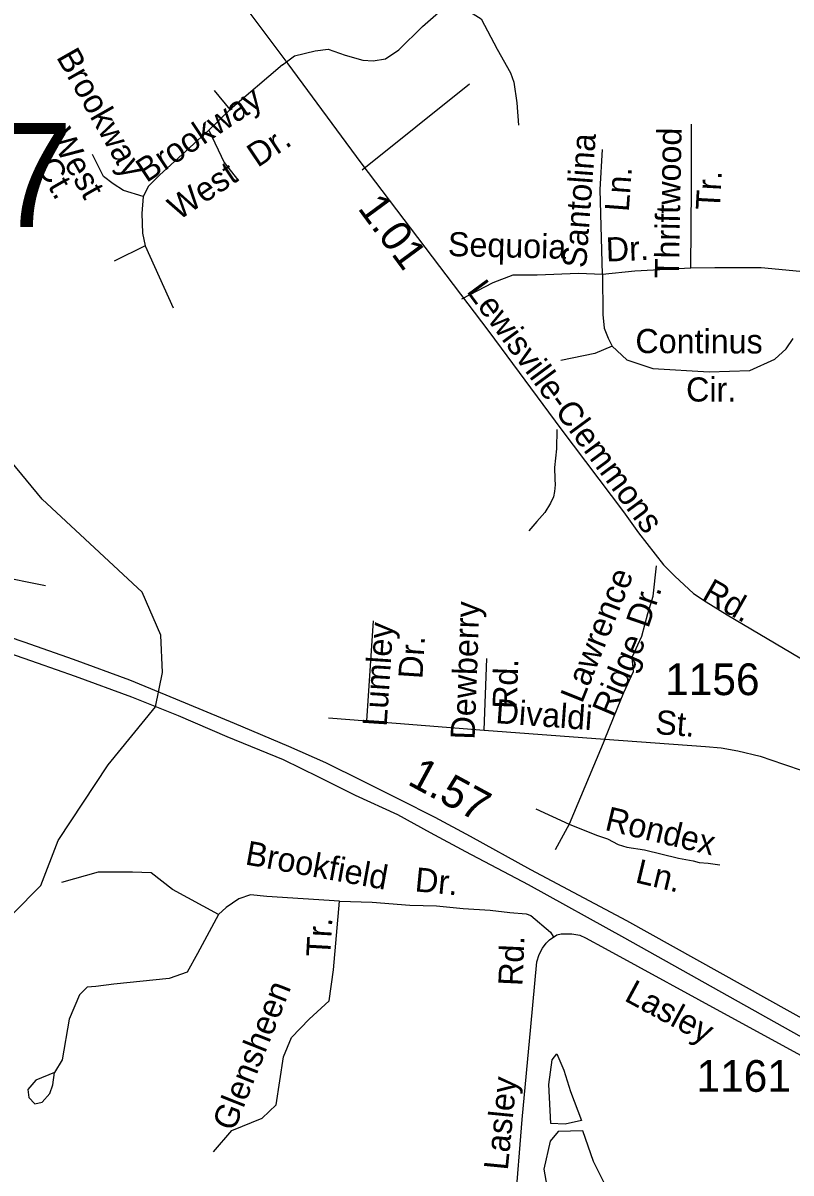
# Model space of a CAD drawing. Extents: x 1547597 to 1699558, y 810033 to 920809.
# Drawn here: x 1580417 to 1583442, y 851817 to 856344 of the extents above; entities that cross this region are included whole.
import ezdxf

# ---------------------------------------------------------------- set-up
doc = ezdxf.new("R2010")
doc.units = 0
for name, color, linetype in [('Exist Hydrographic Misc Water Feature', 7, 'Continuous'), ('Exist Road Non-System Type 51', 7, 'Continuous'), ('Exist Road Non-System Type 51 Label', 7, 'Continuous'), ('Exist Road Primary US Divided Attributed', 7, 'Continuous'), ('Exist Road Primary US Mileage Hundredths English Label', 7, 'Continuous'), ('Exist Road Secondary Mileage Hundredths English Label', 7, 'Continuous'), ('Exist Road Secondary Structure Standard Bridge Number Label', 7, 'Continuous'), ('Exist Road Secondary Type 51 Attributed', 7, 'Continuous'), ('Exist Road Secondary Type 51 Label', 7, 'Continuous'), ('Exist Road Secondary Type 51 Number Label', 7, 'Continuous')]:
    doc.layers.add(name, color=color, linetype=linetype)

msp = doc.modelspace()

# ---------------------------------------------------------------- linework, layer by layer
at = {"layer": 'Exist Hydrographic Misc Water Feature'}
for points in [[(1580376.5, 852836.6), (1580486.5, 852949.2), (1580555.5, 853125.1), (1580751.5, 853423.1), (1580938.5, 853652.4), (1580965.5, 853786.5), (1580959.6, 853934.3), (1580886.6, 854103.2), (1580491.5, 854469), (1580368.5, 854619.3)], [(1582616.1, 852022.9), (1582551.8, 852009.5), (1582495.6, 852012.1), (1582487.5, 852165), (1582500.9, 852261.6), (1582519.7, 852285.7), (1582546.5, 852221.3), (1582573.3, 852138.2), (1582616.1, 852022.9)], [(1582621.5, 851982.6), (1582525, 851980), (1582492.9, 851942.4), (1582468.8, 851832.4), (1582490.2, 851706.4), (1582509, 851682.2), (1582586.7, 851698.3), (1582672.4, 851719.8), (1582720.7, 851749.3), (1582664.4, 851861.9), (1582621.5, 851982.6)]]:
    msp.add_lwpolyline(points, dxfattribs=at)
at = {"layer": 'Exist Road Non-System Type 51'}
for p, q in [((1582221.8, 856359.7), (1582284.1, 856240.8)), ((1581438.2, 856179.9), (1581232.5, 856003.1)), ((1581752.5, 855766.1), (1582175.9, 856104)), ((1581232.5, 856003.1), (1581171.6, 856078.5)), ((1581232.5, 856003.1), (1581148.5, 855921.9)), ((1580897.9, 855466.8), (1580776.2, 855405.9)), ((1580897.9, 855466.8), (1581008, 855223.3)), ((1581771.6, 853596.3), (1581797.4, 853990.2)), ((1582233.3, 853559.7), (1582243.4, 853841.7)), ((1581619.8, 853608.6), (1581771.6, 853596.3)), ((1581771.6, 853596.3), (1582233.3, 853559.7)), ((1582709.1, 853524.7), (1582568, 853190.5)), ((1582437, 853250.6), (1582568, 853190.5)), ((1582568, 853190.5), (1582512.6, 853089.4)), ((1581639.9, 852616.8), (1581663.5, 852887)), ((1581622.5, 852494.9), (1581639.9, 852616.8)), ((1581544.1, 852422.3), (1581622.5, 852494.9)), ((1581474.5, 852349.7), (1581544.1, 852422.3)), ((1581442.6, 852274.2), (1581474.5, 852349.7)), ((1581413.6, 852085.5), (1581442.6, 852274.2)), ((1581358.5, 852033.2), (1581413.6, 852085.5)), ((1581239.5, 851983.9), (1581358.5, 852033.2)), ((1581167, 851899.7), (1581239.5, 851983.9))]:
    msp.add_line(p, q, dxfattribs=at)
for points in [[(1581438.2, 856179.9), (1581486, 856214.7), (1581567.1, 856235), (1581619.2, 856240.8), (1581685.9, 856217.6), (1581755.4, 856197.3), (1581796, 856194.4), (1581845.2, 856203.1), (1581897.4, 856237.9), (1581990.1, 856330.7), (1582053.8, 856385.7), (1582088.6, 856397.3), (1582137.8, 856397.3), (1582190, 856379.9), (1582221.8, 856359.7)], [(1582284.1, 856240.8), (1582336.3, 856148), (1582350.7, 856110.4), (1582362.3, 856029.2), (1582368.1, 855942.2)], [(1581148.5, 855921.9), (1580954.4, 855745.1), (1580910.9, 855701.6), (1580890.6, 855661)], [(1581148.5, 855921.9), (1581209.3, 855794.4), (1581261.4, 855727.7)], [(1583047.7, 855378.5), (1583049.9, 855697.7), (1583049.9, 855945.4)], [(1580890.6, 855661), (1580812.4, 855684.2), (1580771.8, 855710.3), (1580734.2, 855739.3), (1580690.7, 855826.3)], [(1582699, 855353.7), (1582689.9, 855688.7), (1582698.9, 855846.4)], [(1580890.6, 855661), (1580884.8, 855594.4), (1580887.7, 855516.1), (1580897.9, 855466.8)], [(1583047.7, 855378.5), (1582827.2, 855366.7), (1582699, 855353.7)], [(1583532.3, 855359.9), (1583324.4, 855380.7), (1583142.2, 855380.7), (1583047.7, 855378.5)], [(1582699, 855353.7), (1582604.8, 855357.8), (1582442.4, 855351), (1582346.1, 855351.1), (1582266.9, 855321.7), (1582143.6, 855256.5)], [(1582699, 855353.7), (1582701.2, 855196.1), (1582705.7, 855142), (1582721.5, 855103.8), (1582737.2, 855072)], [(1582737.2, 855072), (1582795.7, 855018.2), (1582897, 854984.4), (1583119.7, 854970.9), (1583279.4, 854975.4), (1583378.4, 855020.4), (1583423.4, 855061), (1583450.4, 855101.3)], [(1579460.1, 855087.4), (1579518.8, 854945.8), (1579642.2, 854705.3), (1579772.1, 854445.4), (1579869.5, 854299.1), (1579889, 854247.2), (1579908.4, 854230.9), (1579979.9, 854227.7), (1580113, 854208.2), (1580505.9, 854130.2)], [(1582737.2, 855072), (1582669.7, 855042.7), (1582534.7, 855015.7)], [(1582519.3, 854744.2), (1582517.5, 854668), (1582510.4, 854594.1), (1582511.7, 854548), (1582513.4, 854526), (1582510.9, 854500), (1582506.7, 854478.1), (1582494.4, 854454.3), (1582471.8, 854416.6), (1582441.3, 854381), (1582408.7, 854345.4)], [(1582709.1, 853524.7), (1582756.7, 853644.2), (1582783.6, 853707.7), (1582820.9, 853791.4), (1582815.8, 853846.9), (1582854.3, 853930.1), (1582877.6, 854019.9), (1582899.5, 854087.6), (1582912, 854207.3)], [(1582233.3, 853559.7), (1582709.1, 853524.7), (1583104.7, 853495.1)], [(1583104.7, 853495.1), (1583166.6, 853490.2), (1583232.7, 853479.3), (1583320.3, 853457.9), (1583411.9, 853426.6), (1583489.6, 853399.4), (1583559, 853370.4), (1583636.7, 853343.2), (1583712.6, 853322), (1583790.3, 853307.1), (1583850.2, 853300.1), (1583914.2, 853291.1), (1584292.4, 853289.7)], [(1582568, 853190.5), (1582675.4, 853147.1), (1582719.4, 853132.4), (1582761.1, 853109.8), (1582794.9, 853099.3), (1582864.7, 853088.3), (1582998.4, 853056.4), (1583056.2, 853045.6), (1583080.1, 853039.1), (1583116, 853036.6), (1583162.1, 853030)], [(1581186.7, 852834.7), (1581005.2, 852933.2), (1580922.1, 852997.8), (1580848.3, 853000.9), (1580713, 853000.9), (1580568.4, 852960.9)], [(1581663.5, 852887), (1581377.4, 852905.5), (1581312.8, 852911.6), (1581266.7, 852896.2), (1581217.5, 852862.4), (1581186.7, 852834.7)], [(1581663.5, 852887), (1581792.2, 852882.4), (1581940.4, 852871.6), (1582045.2, 852868.1), (1582151.1, 852858.6), (1582257, 852851), (1582334.9, 852841.9), (1582399, 852837), (1582416.9, 852830.2), (1582494.8, 852765.1), (1582505.4, 852747.3)], [(1581186.7, 852834.7), (1581103.6, 852680.7), (1581063.6, 852606.8), (1580992.9, 852582.2), (1580774.5, 852560.7), (1580703.7, 852551.4), (1580669.9, 852548.3), (1580639.1, 852517.6), (1580599.1, 852422.1), (1580571.5, 852262), (1580540.7, 852212.8)], [(1580540.7, 852212.8), (1580466.9, 852182), (1580436.1, 852145), (1580439.2, 852114.3), (1580463.8, 852089.6), (1580491.5, 852095.8), (1580522.2, 852129.7), (1580534.5, 852163.5), (1580540.7, 852212.8)]]:
    msp.add_lwpolyline(points, dxfattribs=at)
at = {"layer": 'Exist Road Primary US Divided Attributed'}
for points in [[(1584974.1, 851611.8), (1584724.8, 851735.3), (1582795.5, 852809.6), (1582416.9, 853010.1), (1582179.2, 853141), (1582040, 853216.5), (1581899.7, 853287.3), (1581755.2, 853359.2), (1581610.1, 853431.2), (1581464.4, 853496.1), (1581249.7, 853586.9), (1581019.1, 853682.4), (1580837.5, 853756.7), (1580615.2, 853838.1), (1580421.7, 853906.5), (1580197, 853983.2), (1578615.9, 854532.9)], [(1578489.7, 854501), (1578601.1, 854463.3), (1580008.3, 853986.7), (1580472.4, 853825.1), (1580622.2, 853773.2), (1580843.4, 853691.9), (1581027.4, 853617.5), (1581220.2, 853535), (1581440.8, 853444.2), (1581580.6, 853375.7), (1581724.5, 853303.8), (1581891.4, 853228.3), (1582021.1, 853157.5), (1582160.3, 853082), (1582406.3, 852952.3), (1582786.1, 852742.3), (1584705.4, 851668.3), (1584967.6, 851548.7)]]:
    msp.add_lwpolyline(points, dxfattribs=at)
at = {"layer": 'Exist Road Secondary Type 51 Attributed'}
for points in [[(1581306.1, 856387.5), (1581459.7, 856183.6), (1581746.8, 855793.5), (1582252, 855129.1), (1582535.1, 854745.8), (1582782.2, 854419.6), (1582840.6, 854337), (1582940, 854210.3), (1582983.6, 854166.6), (1583057.6, 854097.6), (1583107.8, 854065.2), (1583190.9, 854013.9), (1583476.4, 853845.2), (1583627.9, 853770.9), (1583730.6, 853732), (1583837.6, 853700.7), (1583951.4, 853678.3), (1584043.1, 853670), (1584135.1, 853665.9), (1584352.8, 853684.2)], [(1582354.7, 851683.1), (1582382.4, 852027), (1582416.6, 852392.6), (1582441.1, 852647.4), (1582450.5, 852677.5), (1582463.5, 852702.2), (1582477.6, 852721.7), (1582490.6, 852734.7), (1582518.9, 852754.1), (1582536, 852757.7), (1582578.5, 852758.9), (1582609.7, 852752.4), (1582632.1, 852742.3), (1582710.3, 852700.5), (1583205.1, 852430.4), (1584005.1, 851995.1), (1584268.4, 851843.1), (1584397, 851777.5)]]:
    msp.add_lwpolyline(points, dxfattribs=at)

# ---------------------------------------------------------------- texts
at = {"layer": 'Exist Road Non-System Type 51 Label'}
for s, rotation, p in [('Brookway', 299.5607, (1580546, 856210)), ('Brookway', 33.7498, (1580903.2, 855713.2)), ('West', 299.5607, (1580517.5, 855895.5)), ('Thriftwood', 88.931, (1582999.9, 855338.3)), ('Dr.', 33.7498, (1581340.7, 855772.9)), ('Santolina', 85.776, (1582634.6, 855377.5)), ('Ct.', 299.5607, (1580468, 855782.1)), ('West', 33.7498, (1581029, 855564.6)), ('Ln.', 85.776, (1582802.6, 855598.9)), ('Tr.', 86.9239, (1583161.3, 855605.8)), ('Sequoia', 358.6497, (1582089.6, 855426.5)), ('Dr.', 2.2751, (1582714.3, 855404.6)), ('Continus', 359.8126, (1582828.8, 855044.5)), ('Cir.', 0.0525, (1583028.7, 854853.7)), ('Lawrence', 68.2201, (1582618.8, 853662.1)), ('Dr.', 70.9735, (1582879.3, 853958)), ('Dewberry', 87.9484, (1582195.6, 853521.9)), ('Lumley', 86.2525, (1581849, 853572.5)), ('Ridge', 67.1105, (1582742.7, 853607)), ('Dr.', 86.2525, (1581989.5, 853760)), ('Rd.', 87.9484, (1582360.8, 853642.3)), ('Divaldi', 355.7929, (1582275.9, 853588)), ('St.', 355.721, (1582904.9, 853545.2)), ('Rondex', 346.5807, (1582704.6, 853168)), ('Brookfield', 349.7251, (1581288.2, 853032)), ('Dr.', 354.5222, (1581957.6, 852925.9)), ('Ln.', 346.5807, (1582824.3, 852961.5)), ('Tr.', 86.7679, (1581626.8, 852665.8)), ('Glensheen', 68.4084, (1581248.1, 851977.1))]:
    msp.add_text(s, height=95, rotation=rotation, dxfattribs=at).set_placement(p)
at = {"layer": 'Exist Road Primary US Mileage Hundredths English Label'}
msp.add_text('1.57', height=125, rotation=331.5258, dxfattribs=at).set_placement((1581926.6, 853349.1))
at = {"layer": 'Exist Road Secondary Mileage Hundredths English Label'}
msp.add_text('1.01', height=120, rotation=306.3755, dxfattribs=at).set_placement((1581732.5, 855614.3))
at = {"layer": 'Exist Road Secondary Structure Standard Bridge Number Label'}
msp.add_text('187', height=410.1, dxfattribs=at).set_placement((1579697.9, 855540.8))
at = {"layer": 'Exist Road Secondary Type 51 Label'}
for s, rotation, p in [('Lewisville-Clemmons', 306.3755, (1582161.4, 855287.3)), ('Rd.', 330.3599, (1583086.3, 854078)), ('Rd.', 87.3671, (1582383.5, 852551.5)), ('Lasley', 331.5658, (1582780.9, 852497.7)), ('Lasley', 84.4187, (1582326.1, 851825.2))]:
    msp.add_text(s, height=95, rotation=rotation, dxfattribs=at).set_placement(p)
at = {"layer": 'Exist Road Secondary Type 51 Number Label'}
for s, p in [('1156', (1582946.1, 853697.9)), ('1161', (1583069.7, 852136.3))]:
    msp.add_text(s, height=125, dxfattribs=at).set_placement(p)

doc.saveas('drawing.dxf')
